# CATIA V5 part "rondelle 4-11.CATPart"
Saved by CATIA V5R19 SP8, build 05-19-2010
Part number: rondelle 4-11
Revision: ANY
Definition: UNKNOWN
Nomenclature: rondelle 4-11
Source: Unknown
Bounding box of the stored display mesh (mm): x -5.5 to 5.5, y -5.491 to 5.491, z 0 to 0.5
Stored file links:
  D:\Documents\1_Travail\1 - ac-limoges.fr\ac-limoges.fr\Emmanuel Maynard - STI2D_Turgot\2 -2I2D\2_SEQUENCE_Serrure_Biométrique\5-Spé_ITEC\Serrure_Bio_Eleve\rondelle 4-11.CATPart
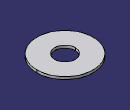
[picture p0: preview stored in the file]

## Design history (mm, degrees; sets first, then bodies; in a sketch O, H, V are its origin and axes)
Body1 "Extrusion1" (main body)
  Solid1: solid without history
